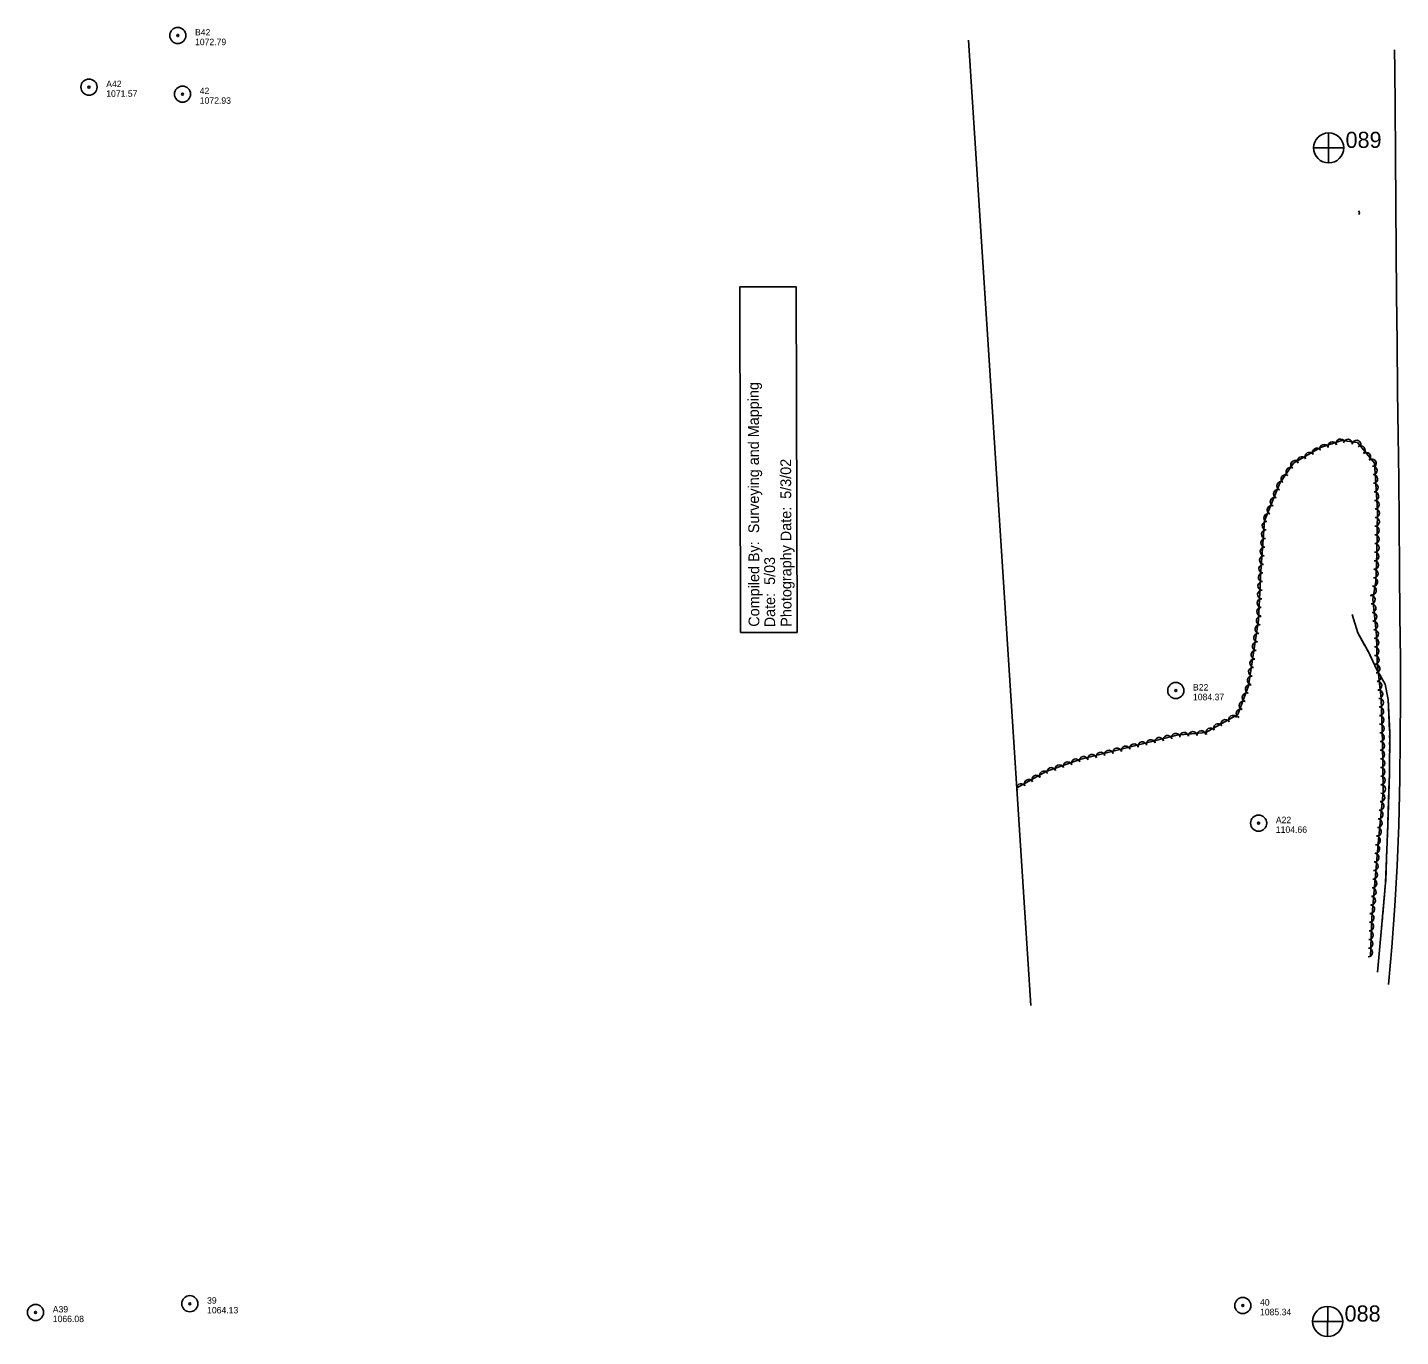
# Model space of a CAD drawing. Extents: x 296462 to 298813, y 30517 to 31770.
# Drawn here: x 296462 to 297738, y 30553 to 31770 of the extents above; entities that cross this region are included whole.
import ezdxf

# ---------------------------------------------------------------- set-up
doc = ezdxf.new("R2010")
doc.units = 0
for name, color, linetype in [('Level 10', 7, 'Continuous'), ('Level 11', 7, 'Continuous'), ('Level 15', 7, 'Continuous'), ('Level 18', 7, 'Continuous'), ('Level 19', 7, 'Continuous'), ('Level 4', 7, 'Continuous'), ('Level 6', 7, 'Continuous')]:
    doc.layers.add(name, color=color, linetype=linetype)

msp = doc.modelspace()

# ---------------------------------------------------------------- linework, layer by layer
at = {"layer": 'Level 10'}
msp.add_lwpolyline([(297124.7, 31207.9), (297177.1, 31208), (297176.3, 31529.3), (297123.9, 31529.2)], close=True, dxfattribs=at)
at = {"layer": 'Level 11'}
msp.add_lwpolyline([(297726.9, 30880.8), (297730, 30915.4), (297732.6, 30954), (297734.8, 30991.1), (297736.4, 31028.9), (297737.3, 31072), (297737.8, 31109.1), (297738, 31147.8), (297737.9, 31183.2), (297737.4, 31223.8), (297737, 31265.7), (297736.7, 31310.8), (297736.3, 31350.5), (297735.7, 31391.4), (297735.2, 31432), (297734.8, 31477.5), (297734.4, 31521.8), (297734, 31563), (297733.7, 31604.7), (297733.3, 31652.6), (297733, 31695.9), (297732.7, 31732), (297732.5, 31749.5)], dxfattribs=at)
at = {"layer": 'Level 15'}
msp.add_arc((297697.8, 31598.1), 2.06, 309.3024, 55.5419, dxfattribs=at)
at = {"layer": 'Level 18'}
msp.add_lwpolyline([(297710, 30906.5), (297711.4, 30942.8), (297717.4, 31015.2), (297722, 31059.7), (297721.1, 31105.9), (297720.1, 31146.7), (297716.2, 31180.4), (297715.7, 31205.5), (297712.4, 31238.9), (297714.9, 31255.2), (297716.1, 31281.7), (297716.5, 31321.4), (297713.9, 31365.4), (297698, 31384.6), (297683.4, 31386.4), (297663.7, 31379.8), (297638.6, 31365.5), (297625.8, 31346.7), (297611.7, 31311.8), (297608.1, 31264.9), (297606, 31219.5), (297596.7, 31158.4), (297586.7, 31131.8), (297556.9, 31115.1), (297530.3, 31112.6), (297475.8, 31098.9), (297439.8, 31089.9), (297408.8, 31078.8), (297384.1, 31065.1), (297381.5, 31063.2)], dxfattribs=at)
for centre, start, end in [((297667, 31378.7), 18.69, 198.6746), ((297674.6, 31381.2), 18.69, 198.6746), ((297682.2, 31383.8), 18.69, 198.6746), ((297689.1, 31383.6), 352.792, 172.7767), ((297697.1, 31382.6), 352.792, 172.7767), ((297701.1, 31377.5), 309.7402, 129.7249), ((297640.1, 31363.9), 55.6059, 235.5905), ((297646.2, 31367.4), 29.7083, 209.693), ((297653.2, 31371.4), 29.7083, 209.693), ((297660.2, 31375.3), 29.7083, 209.693), ((297706.2, 31371.4), 309.7402, 129.7249), ((297711.4, 31365.2), 309.7402, 129.7249), ((297631, 31350.6), 55.6059, 235.5905), ((297635.5, 31357.3), 55.6059, 235.5905), ((297712.2, 31358.7), 273.4073, 93.392), ((297712.7, 31350.7), 273.4073, 93.392), ((297627, 31344.2), 68.0574, 248.042), ((297713.1, 31342.7), 273.4073, 93.392), ((297621, 31329.3), 68.0574, 248.042), ((297624, 31336.8), 68.0574, 248.042), ((297713.6, 31334.7), 273.4073, 93.392), ((297714.1, 31326.7), 273.4073, 93.392), ((297615, 31314.4), 68.0574, 248.042), ((297618, 31321.9), 68.0574, 248.042), ((297714.4, 31318.8), 269.3598, 89.3445), ((297612.8, 31299.3), 85.5674, 265.552), ((297613.5, 31307.3), 85.5674, 265.552), ((297714.3, 31310.8), 269.3598, 89.3445), ((297714.2, 31302.7), 269.3598, 89.3445), ((297612.2, 31291.3), 85.5674, 265.552), ((297714, 31286.7), 269.3598, 89.3445), ((297714.1, 31294.7), 269.3598, 89.3445), ((297611, 31275.3), 85.5674, 265.552), ((297611.6, 31283.3), 85.5674, 265.552), ((297713.8, 31278.7), 267.4611, 87.4458), ((297610.4, 31267.3), 85.5674, 265.552), ((297713.1, 31262.7), 267.4611, 87.4458), ((297713.5, 31270.7), 267.4611, 87.4458), ((297609.5, 31251.3), 87.3472, 267.3319), ((297609.9, 31259.3), 87.3472, 267.3319), ((297712.7, 31254.9), 261.3079, 81.2926), ((297608.8, 31235.3), 87.3472, 267.3319), ((297609.2, 31243.3), 87.3472, 267.3319), ((297710.3, 31238.5), 275.6259, 95.6106), ((297711.5, 31247), 261.3079, 81.2926), ((297608.4, 31227.3), 87.3472, 267.3319), ((297711.1, 31230.5), 275.6259, 95.6106), ((297711.9, 31222.5), 275.6259, 95.6106), ((297606.8, 31211.1), 81.4071, 261.3918), ((297608, 31219), 81.4071, 261.3918), ((297712.7, 31214.5), 275.6259, 95.6106), ((297605.6, 31203.2), 81.4071, 261.3918), ((297713.5, 31206.5), 275.6259, 95.6106), ((297713.7, 31198.7), 271.1785, 91.1632), ((297603.2, 31187.3), 81.4071, 261.3918), ((297604.4, 31195.2), 81.4071, 261.3918), ((297713.9, 31190.6), 271.1785, 91.1632), ((297600.8, 31171.4), 81.4071, 261.3918), ((297602, 31179.3), 81.4071, 261.3918), ((297714, 31182.6), 271.1785, 91.1632), ((297714.8, 31174.4), 276.5725, 96.5572), ((297599.6, 31163.5), 81.4071, 261.3918), ((297715.7, 31166.5), 276.5725, 96.5572), ((297594.9, 31147.7), 69.3528, 249.3374), ((297597.8, 31155.2), 69.3528, 249.3374), ((297716.6, 31158.5), 276.5725, 96.5572), ((297717.5, 31150.5), 276.5725, 96.5572), ((297592.1, 31140.2), 69.3528, 249.3374), ((297718.1, 31142.7), 271.4904, 91.475), ((297718.3, 31134.7), 271.4904, 91.475), ((297575.2, 31123), 29.2061, 209.1908), ((297582.2, 31126.9), 29.2061, 209.1908), ((297589.3, 31132.7), 69.3528, 249.3374), ((297718.5, 31126.6), 271.4904, 91.475), ((297521.5, 31108.2), 14.1346, 194.1193), ((297529.2, 31110.2), 14.1346, 194.1193), ((297536.9, 31111.1), 5.4157, 185.4003), ((297544.9, 31111.9), 5.4157, 185.4003), ((297552.9, 31112.6), 5.4157, 185.4003), ((297561.2, 31115.1), 29.2061, 209.1908), ((297568.2, 31119.1), 29.2061, 209.1908), ((297718.7, 31118.6), 271.4904, 91.475), ((297718.9, 31110.6), 271.4904, 91.475), ((297474.7, 31096.5), 14.051, 194.0357), ((297482.5, 31098.4), 14.1346, 194.1193), ((297490.3, 31100.4), 14.1346, 194.1193), ((297498.1, 31102.4), 14.1346, 194.1193), ((297505.9, 31104.3), 14.1346, 194.1193), ((297513.7, 31106.3), 14.1346, 194.1193), ((297719.1, 31102.6), 271.1081, 91.0928), ((297428.6, 31083.7), 19.6642, 199.6489), ((297436.1, 31086.4), 19.6642, 199.6489), ((297443.6, 31088.7), 14.051, 194.0357), ((297451.4, 31090.6), 14.051, 194.0357), ((297459.2, 31092.6), 14.051, 194.0357), ((297466.9, 31094.5), 14.051, 194.0357), ((297719.2, 31094.6), 271.1081, 91.0928), ((297719.4, 31086.5), 271.1081, 91.0928), ((297399.4, 31071.2), 29.1091, 209.0937), ((297406.5, 31075.1), 29.1091, 209.0937), ((297413.4, 31078.3), 19.6642, 199.6489), ((297421, 31081), 19.6642, 199.6489), ((297719.5, 31078.5), 271.1081, 91.0928), ((297719.7, 31070.5), 271.1081, 91.0928), ((297385.4, 31063.4), 29.1091, 174.9535), ((297385.4, 31063.4), 192.431, 209.0937), ((297379.1, 31058.9), 35.695, 52.3948), ((297392.4, 31067.3), 29.1091, 209.0937), ((297719.9, 31062.4), 271.1081, 91.0928), ((297718.5, 31046.7), 264.0693, 84.054), ((297719.4, 31054.7), 264.0693, 84.054), ((297717.7, 31038.7), 264.0693, 84.054), ((297716.1, 31022.8), 264.0693, 84.054), ((297716.9, 31030.7), 264.0693, 84.054), ((297714.6, 31006.7), 265.2584, 85.2431), ((297715.2, 31014.7), 265.2584, 85.2431), ((297713.9, 30998.7), 265.2584, 85.2431), ((297712.6, 30982.7), 265.2584, 85.2431), ((297713.2, 30990.7), 265.2584, 85.2431), ((297711.9, 30974.7), 265.2584, 85.2431), ((297710.6, 30958.7), 265.2584, 85.2431), ((297711.2, 30966.7), 265.2584, 85.2431), ((297709.3, 30942.6), 267.8299, 87.8146), ((297709.9, 30950.7), 265.2584, 85.2431), ((297709, 30934.6), 267.8299, 87.8146), ((297708.3, 30918.6), 267.8299, 87.8146), ((297708.6, 30926.6), 267.8299, 87.8146), ((297708, 30910.5), 267.8299, 87.8146)]:
    msp.add_arc(centre, 4.01, start, end, dxfattribs=at)
at = {"layer": 'Level 19'}
for points in [[(297716.6, 30892.1), (297719.7, 30926.4), (297724.1, 30975.1), (297726.1, 31028.6), (297727.6, 31077), (297727.9, 31115), (297726.5, 31145.8), (297723.6, 31160), (297716.1, 31173.2), (297708.4, 31189.5), (297698.2, 31207.7), (297693.1, 31224.6)], [(297704.6, 31196.3), (297698.2, 31207.7), (297693.1, 31224.6)], [(297707.7, 31190.7), (297706.7, 31192.5)], [(297710.5, 31185), (297709.6, 31186.9)], [(297713.2, 31179.3), (297712.3, 31181.2)], [(297726.2, 31147.3), (297723.6, 31160), (297716.1, 31173.2), (297715.1, 31175.5)], [(297727.8, 31116.4), (297726.5, 31145.8), (297726.2, 31147.3)], [(297727.8, 31110.1), (297727.8, 31112.2)], [(297727.7, 31097.3), (297727.7, 31099.4)], [(297727.8, 31103.7), (297727.8, 31105.8)], [(297727.1, 31062.1), (297727.6, 31077), (297727.7, 31093)], [(297726.2, 31031.3), (297727.1, 31062.1)], [(297726, 31024.9), (297726.1, 31027)], [(297725.5, 31012.1), (297725.6, 31014.2)], [(297725.7, 31018.5), (297725.8, 31020.6)], [(297724.2, 30977), (297725.3, 31007.8)], [(297721.5, 30946.2), (297724.1, 30975.1), (297724.2, 30977)], [(297720.3, 30933.5), (297720.5, 30935.6)], [(297720.9, 30939.8), (297721.1, 30942)], [(297716.6, 30892.1), (297719.3, 30922.9)], [(297719.7, 30927.1), (297719.9, 30929.2)]]:
    msp.add_lwpolyline(points, dxfattribs=at)
at = {"layer": 'Level 4'}
for p, q in [((297671.2, 31672.4), (297671.1, 31644.6)), ((297657.2, 31658.4), (297685.2, 31658.4)), ((297670.3, 30581.5), (297670.2, 30553.7)), ((297656.4, 30567.5), (297684.3, 30567.5))]:
    msp.add_line(p, q, dxfattribs=at)
msp.add_lwpolyline([(297336.6, 31758.4), (297394.5, 30861.3)], dxfattribs=at)
for centre in [(297671.2, 31658.4), (297670.3, 30567.5)]:
    msp.add_circle(centre, 14, dxfattribs=at)
at = {"layer": 'Level 6'}
for centre, radius in [((296601.6, 31762.9), 7.5), ((296601.6, 31762.9), 0.96), ((296519.1, 31714.9), 7.5), ((296519.1, 31714.9), 0.96), ((296606, 31708.4), 7.5), ((296606, 31708.4), 0.96), ((297529.1, 31154), 7.5), ((297529.1, 31154), 0.96), ((297606.1, 31030.7), 7.5), ((297606.1, 31030.7), 0.96), ((296612.8, 30584), 7.5), ((297591.4, 30582.3), 7.5), ((296469.4, 30575.9), 7.5), ((296469.4, 30575.9), 0.96), ((296612.8, 30584), 0.96), ((297591.4, 30582.3), 0.96)]:
    msp.add_circle(centre, radius, dxfattribs=at)

# ---------------------------------------------------------------- texts
at = {"layer": 'Level 10'}
for s, p in [('Compiled By:  Surveying and Mapping', (297142.1, 31213.3)), ('Photography Date:  5/3/02  ', (297172, 31213.3)), ('Date:  5/03    ', (297156.8, 31212.8))]:
    msp.add_text(s, height=10, rotation=90.1424, dxfattribs=at).set_placement(p)
at = {"layer": 'Level 4'}
for s, p in [('089', (297686.9, 31658.4)), ('088', (297686, 30567.4))]:
    msp.add_text(s, height=15, dxfattribs=at).set_placement(p)
at = {"layer": 'Level 6'}
for s, p in [('B42', (296617.6, 31762.9)), ('1072.79', (296617.6, 31753.9)), ('A42', (296535.1, 31714.9)), ('1071.57', (296535.1, 31705.9)), ('42', (296622, 31708.4)), ('1072.93', (296622, 31699.4)), ('B22', (297545.1, 31154)), ('1084.37', (297545.1, 31145)), ('A22', (297622.1, 31030.7)), ('1104.66', (297622.1, 31021.7)), ('39', (296628.8, 30584)), ('A39', (296485.4, 30575.9)), ('1064.13', (296628.8, 30575)), ('40', (297607.4, 30582.3)), ('1085.34', (297607.4, 30573.3)), ('1066.08', (296485.4, 30566.9))]:
    msp.add_text(s, height=6, dxfattribs=at).set_placement(p)

doc.saveas('drawing.dxf')
